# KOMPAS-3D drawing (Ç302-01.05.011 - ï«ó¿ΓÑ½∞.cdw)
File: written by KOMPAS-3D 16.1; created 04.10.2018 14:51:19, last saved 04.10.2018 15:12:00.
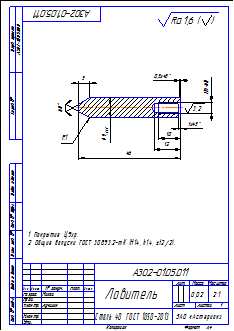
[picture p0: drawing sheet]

Sheet 1: A4, portrait

Title block, sheet 1: name: Ловитель; designation: А302-01.05.011; material: Сталь 40  ГОСТ 1050-2013; mass: 0,02; scale: 2:1; sheets: 1; organisation: ЗАО «Астерион»; sheet format: A4; stored path: \\192.168.87.28\Konstructor_doc\Мембранные насосы\Мембранный электропривод\А302-00.00.000 - ASTRA-302 (МЭ200)\3Д ПВХ\А302-01.05.011 - Ловитель.cdw; drawn by: Милов; technical control: Лучихин

Views: Вид 1, Местный разрез 1, Спереди, Проекционный вид 2
Referenced files in \\192.168.87.28\Konstructor_doc\Мембранные насосы\Мембранный электропривод\А302-00.00.000 - ASTRA-302 (МЭ200)\3Д ПВХ\: А302-01.05.011 - Ловитель.m3d
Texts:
  Покрытие: Ц9хр.
  Общие допуски ГОСТ 30893.2-mK (H14, h14,  t2/2).
  Ra 1,6
  Ra 1,6 ( )
Dimensions and other numbers on the sheet: -6Н; 5; 3,2; 1; 0,5; 46; 9; 10; 12; 2:1; 0,02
